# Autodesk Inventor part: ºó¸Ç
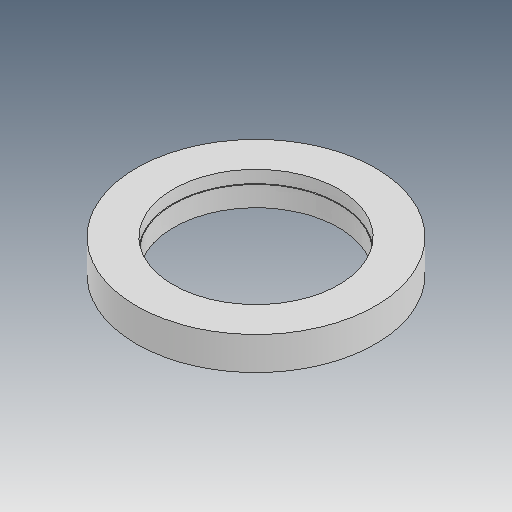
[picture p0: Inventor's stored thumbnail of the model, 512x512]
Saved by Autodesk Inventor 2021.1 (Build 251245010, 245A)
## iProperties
Created: 2019-04
Part Number: ºó¸Ç
Material: Ogólny
Document SubType Name: Modeling
Designer: user
Density: 1 g/cm^3
Appearance: Domyślna
Author: user
Revision Number: ÈÎºÎ
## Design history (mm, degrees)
feature "Ðý×ª1"
node "Bryła1"
